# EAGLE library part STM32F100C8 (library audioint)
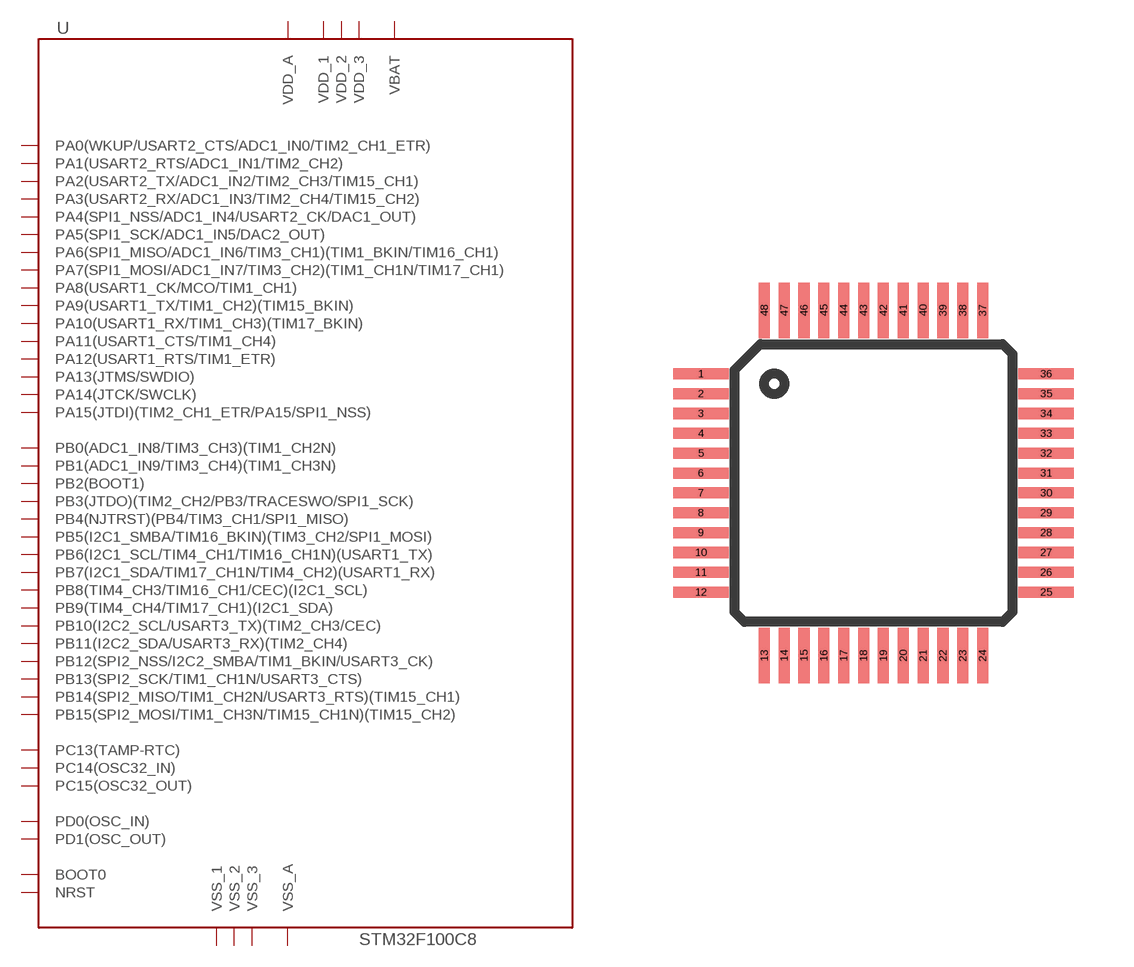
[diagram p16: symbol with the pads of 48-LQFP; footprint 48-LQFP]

Designator prefix -

## STM32F100C848-LQFP  [48-LQFP]
1  VBAT
2  PC13(TAMP-RTC)
3  PC14(OSC32_IN)
4  PC15(OSC32_OUT)
5  PD0(OSC_IN)
6  PD1(OSC_OUT)
7  NRST
8  VSS_A
9  VDD_A
10  PA0(WKUP/USART2_CTS/ADC1_IN0/TIM2_CH1_ETR)
11  PA1(USART2_RTS/ADC1_IN1/TIM2_CH2)
12  PA2(USART2_TX/ADC1_IN2/TIM2_CH3/TIM15_CH1)
13  PA3(USART2_RX/ADC1_IN3/TIM2_CH4/TIM15_CH2)
14  PA4(SPI1_NSS/ADC1_IN4/USART2_CK/DAC1_OUT)
15  PA5(SPI1_SCK/ADC1_IN5/DAC2_OUT)
16  PA6(SPI1_MISO/ADC1_IN6/TIM3_CH1)(TIM1_BKIN/TIM16_CH1)
17  PA7(SPI1_MOSI/ADC1_IN7/TIM3_CH2)(TIM1_CH1N/TIM17_CH1)
18  PB0(ADC1_IN8/TIM3_CH3)(TIM1_CH2N)
19  PB1(ADC1_IN9/TIM3_CH4)(TIM1_CH3N)
20  PB2(BOOT1)
21  PB10(I2C2_SCL/USART3_TX)(TIM2_CH3/CEC)
22  PB11(I2C2_SDA/USART3_RX)(TIM2_CH4)
23  VSS_1
24  VDD_1
25  PB12(SPI2_NSS/I2C2_SMBA/TIM1_BKIN/USART3_CK)
26  PB13(SPI2_SCK/TIM1_CH1N/USART3_CTS)
27  PB14(SPI2_MISO/TIM1_CH2N/USART3_RTS)(TIM15_CH1)
28  PB15(SPI2_MOSI/TIM1_CH3N/TIM15_CH1N)(TIM15_CH2)
29  PA8(USART1_CK/MCO/TIM1_CH1)
30  PA9(USART1_TX/TIM1_CH2)(TIM15_BKIN)
31  PA10(USART1_RX/TIM1_CH3)(TIM17_BKIN)
32  PA11(USART1_CTS/TIM1_CH4)
33  PA12(USART1_RTS/TIM1_ETR)
34  PA13(JTMS/SWDIO)
35  VSS_2
36  VDD_2
37  PA14(JTCK/SWCLK)
38  PA15(JTDI)(TIM2_CH1_ETR/PA15/SPI1_NSS)
39  PB3(JTDO)(TIM2_CH2/PB3/TRACESWO/SPI1_SCK)
40  PB4(NJTRST)(PB4/TIM3_CH1/SPI1_MISO)
41  PB5(I2C1_SMBA/TIM16_BKIN)(TIM3_CH2/SPI1_MOSI)
42  PB6(I2C1_SCL/TIM4_CH1/TIM16_CH1N)(USART1_TX)
43  PB7(I2C1_SDA/TIM17_CH1N/TIM4_CH2)(USART1_RX)
44  BOOT0
45  PB8(TIM4_CH3/TIM16_CH1/CEC)(I2C1_SCL)
46  PB9(TIM4_CH4/TIM17_CH1)(I2C1_SDA)
47  VSS_3
48  VDD_3

## Footprint 48-LQFP (pad centres in mm)
smd 1.4 x 0.28: 1 -4.35,2.75; 2 -4.35,2.25; 3 -4.35,1.75; 4 -4.35,1.25; 5 -4.35,0.75; 6 -4.35,0.25; 7 -4.35,-0.25; 8 -4.35,-0.75; 9 -4.35,-1.25; 10 -4.35,-1.75; 11 -4.35,-2.25; 12 -4.35,-2.75; 25 4.35,-2.75; 26 4.35,-2.25; 27 4.35,-1.75; 28 4.35,-1.25; 29 4.35,-0.75; 30 4.35,-0.25; 31 4.35,0.25; 32 4.35,0.75; 33 4.35,1.25; 34 4.35,1.75; 35 4.35,2.25; 36 4.35,2.75
smd 0.28 x 1.4: 13 -2.75,-4.35; 14 -2.25,-4.35; 15 -1.75,-4.35; 16 -1.25,-4.35; 17 -0.75,-4.35; 18 -0.25,-4.35; 19 0.25,-4.35; 20 0.75,-4.35; 21 1.25,-4.35; 22 1.75,-4.35; 23 2.25,-4.35; 24 2.75,-4.35; 37 2.75,4.35; 38 2.25,4.35; 39 1.75,4.35; 40 1.25,4.35; 41 0.75,4.35; 42 0.25,4.35; 43 -0.25,4.35; 44 -0.75,4.35; 45 -1.25,4.35; 46 -1.75,4.35; 47 -2.25,4.35; 48 -2.75,4.35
